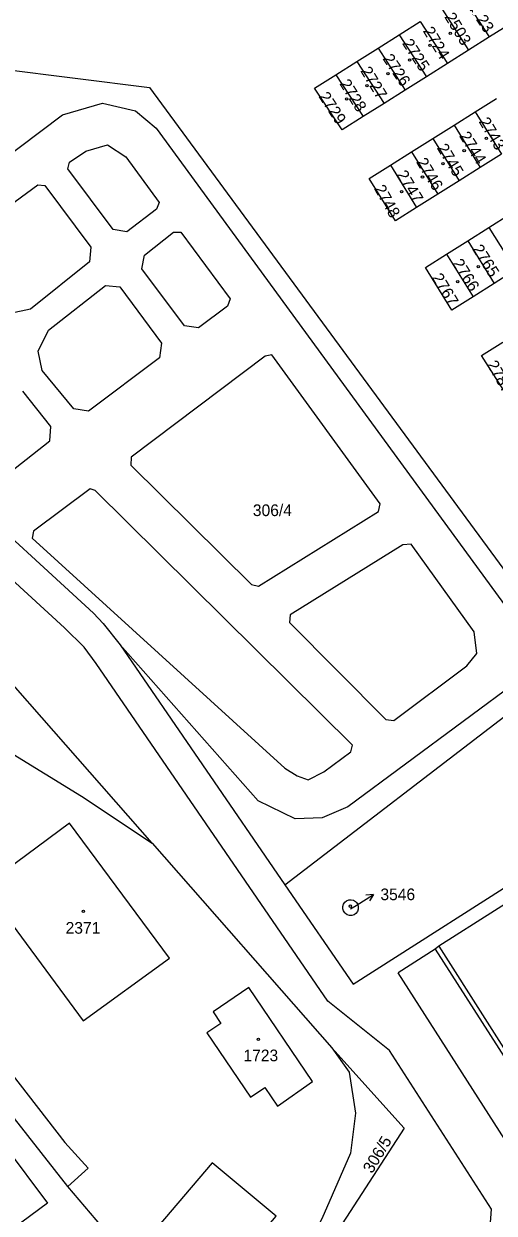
# Model space of a CAD drawing. Extents: x -679220 to -673243, y -1075091 to -1066557.
# Drawn here: x -676246.6 to -676178, y -1072555.7 to -1072382.5 of the extents above; entities that cross this region are included whole.
import ezdxf

# ---------------------------------------------------------------- set-up
doc = ezdxf.new("R2010")
doc.units = 0
for name, color, linetype in [('Hranice parcel', 7, 'Continuous'), ('Parcelní čísla', 7, 'Continuous'), ('Pop  PČ popisy', 7, 'Continuous'), ('Vnitřní kresba', 7, 'Continuous'), ('Značky budov', 7, 'Continuous')]:
    doc.layers.add(name, color=color, linetype=linetype)

msp = doc.modelspace()

# ---------------------------------------------------------------- linework, layer by layer
at = {"layer": 'Hranice parcel'}
for p, q in [((-676178.71, -1072384.44), (-676182.66, -1072378.34)), ((-676185.73, -1072380.27), (-676181.78, -1072386.37)), ((-676191.87, -1072384.13), (-676188.8, -1072382.2)), ((-676188.8, -1072382.2), (-676184.85, -1072388.31)), ((-676175.65, -1072382.51), (-676178.71, -1072384.44)), ((-676194.96, -1072386.07), (-676191.87, -1072384.13)), ((-676191.87, -1072384.13), (-676187.91, -1072390.24)), ((-676178.71, -1072384.44), (-676181.78, -1072386.37)), ((-676198.03, -1072388), (-676194.96, -1072386.07)), ((-676194.96, -1072386.07), (-676190.98, -1072392.18)), ((-676181.78, -1072386.37), (-676184.85, -1072388.31)), ((-676201.11, -1072389.94), (-676198.03, -1072388)), ((-676198.03, -1072388), (-676194.04, -1072394.11)), ((-676184.85, -1072388.31), (-676187.91, -1072390.24)), ((-676201.11, -1072389.94), (-676197.1, -1072396.04)), ((-676187.91, -1072390.24), (-676190.98, -1072392.18)), ((-676190.98, -1072392.18), (-676194.04, -1072394.11)), ((-676180.79, -1072395.35), (-676177.71, -1072393.41)), ((-676194.04, -1072394.11), (-676197.1, -1072396.04)), ((-676183.88, -1072397.29), (-676180.79, -1072395.35)), ((-676180.79, -1072395.35), (-676176.98, -1072401.52)), ((-676186.98, -1072399.23), (-676183.88, -1072397.29)), ((-676183.88, -1072397.29), (-676180.07, -1072403.46)), ((-676190.07, -1072401.17), (-676186.98, -1072399.23)), ((-676186.98, -1072399.23), (-676183.16, -1072405.41)), ((-676193.16, -1072403.11), (-676190.07, -1072401.17)), ((-676190.07, -1072401.17), (-676186.25, -1072407.35)), ((-676176.98, -1072401.52), (-676180.07, -1072403.46)), ((-676193.16, -1072403.11), (-676189.34, -1072409.29)), ((-676180.07, -1072403.46), (-676183.16, -1072405.41)), ((-676183.16, -1072405.41), (-676186.25, -1072407.35)), ((-676186.25, -1072407.35), (-676189.34, -1072409.29)), ((-676178.81, -1072412.19), (-676175.74, -1072410.25)), ((-676181.89, -1072414.14), (-676178.81, -1072412.19)), ((-676178.81, -1072412.19), (-676174.94, -1072418.38)), ((-676184.96, -1072416.09), (-676181.89, -1072414.14)), ((-676181.89, -1072414.14), (-676178.03, -1072420.33)), ((-676184.96, -1072416.09), (-676181.11, -1072422.28)), ((-676174.94, -1072418.38), (-676178.03, -1072420.33)), ((-676178.03, -1072420.33), (-676181.11, -1072422.28)), ((-676208.52, -1072507.9), (-676175.83, -1072482.87)), ((-676227.86, -1072501.86), (-676201.67, -1072531.67)), ((-676231.08, -1072562.45), (-676240.15, -1072551.88))]:
    msp.add_line(p, q, dxfattribs=at)
for points in [[(-676227.86, -1072501.86), (-676299.88, -1072419.89), (-676371.63, -1072338.06)], [(-676393.87, -1072354.27), (-676392.79, -1072356.37), (-676350.62, -1072411.11), (-676336.27, -1072423.2), (-676320.05, -1072433.48), (-676310.5, -1072438.74), (-676297.87, -1072456.58), (-676292.66, -1072479.44), (-676278.01, -1072497.19), (-676240.58, -1072545.43), (-676237.18, -1072549.2), (-676240.15, -1072551.88)], [(-676249.92, -1072389.1), (-676228.26, -1072391.78), (-676166.55, -1072475.76), (-676169.49, -1072478.01)], [(-676197.1, -1072396.04), (-676200.17, -1072397.98), (-676204.19, -1072391.88), (-676201.11, -1072389.94)], [(-676292.07, -1072402.99), (-676279.41, -1072419.22), (-676277.22, -1072423.73), (-676275.71, -1072427.4), (-676272.62, -1072432.59), (-676272.04, -1072433.35), (-676258.47, -1072448.08), (-676256.31, -1072450.13), (-676236.39, -1072468.37), (-676234.99, -1072469.86), (-676232.52, -1072472.99), (-676208.52, -1072507.9)], [(-676189.34, -1072409.29), (-676192.42, -1072411.23), (-676196.25, -1072405.05), (-676193.16, -1072403.11)], [(-676181.11, -1072422.28), (-676184.19, -1072424.23), (-676188.03, -1072418.03), (-676184.96, -1072416.09)], [(-676172.83, -1072435.02), (-676175.93, -1072436.98), (-676179.86, -1072430.85), (-676176.77, -1072428.9)], [(-676179.64, -1072571.39), (-676178.45, -1072555.16), (-676193.28, -1072532.03), (-676202.29, -1072524.88), (-676236.01, -1072475.68), (-676237.75, -1072473.29), (-676240.63, -1072470.5), (-676259.07, -1072453.6)], [(-676240.15, -1072551.88), (-676280.98, -1072499.86), (-676296, -1072482.45), (-676303.18, -1072461.34)], [(-676254.72, -1072484.88), (-676238.18, -1072494.99), (-676227.86, -1072501.86)], [(-676225.34, -1072518.59), (-676239.89, -1072498.95), (-676252.37, -1072508.19), (-676237.91, -1072527.72), (-676225.34, -1072518.59)], [(-676208.52, -1072507.9), (-676198.57, -1072522.38), (-676170.54, -1072504.52), (-676161.87, -1072507.92), (-676139.81, -1072542.54), (-676135.25, -1072539.65)], [(-676136.5, -1072570.82), (-676098.44, -1072546.68), (-676102.53, -1072540.16), (-676108.2, -1072531.13), (-676132.8, -1072546.95), (-676137.84, -1072550.19), (-676139.52, -1072551.27), (-676140.87, -1072552.14), (-676144.06, -1072547.18), (-676144.87, -1072545.92), (-676146.85, -1072542.85), (-676143.02, -1072540.41), (-676162.81, -1072509.22), (-676166.7, -1072511.75), (-676169.87, -1072506.55), (-676186.1, -1072516.87), (-676159.97, -1072557.94)], [(-676199.55, -1072510.23), (-676199.23, -1072510.12), (-676198.89, -1072510.1), (-676198.55, -1072510.18), (-676198.26, -1072510.36), (-676198.1, -1072510.52), (-676197.92, -1072510.81), (-676197.84, -1072511.14), (-676197.85, -1072511.48), (-676197.97, -1072511.81), (-676198.17, -1072512.08), (-676198.44, -1072512.29), (-676198.77, -1072512.39), (-676199.11, -1072512.39), (-676199.44, -1072512.29), (-676199.72, -1072512.1), (-676199.8, -1072512.02), (-676199.99, -1072511.73), (-676200.09, -1072511.41), (-676200.1, -1072511.06), (-676200, -1072510.74), (-676199.81, -1072510.45), (-676199.55, -1072510.23)], [(-676213.54, -1072538.86), (-676211.47, -1072537.46), (-676209.6, -1072540.16), (-676204.48, -1072536.57), (-676213.79, -1072522.87), (-676218.96, -1072526.44), (-676217.84, -1072528.1), (-676219.9, -1072529.5), (-676213.54, -1072538.86)], [(-676201.67, -1072531.67), (-676199.17, -1072535.19), (-676198.24, -1072541.19), (-676198.95, -1072546.98), (-676203.16, -1072556.56), (-676210.92, -1072570.88), (-676218.12, -1072581.78), (-676236.74, -1072601.09), (-676236.52, -1072604.92), (-676236.33, -1072610.64)], [(-676201.67, -1072531.67), (-676191.15, -1072543.36), (-676235.07, -1072611.09)], [(-676257.12, -1072538.94), (-676255.51, -1072537.76), (-676243.1, -1072554.3), (-676269.14, -1072573.49), (-676269.31, -1072573.26)], [(-676223.04, -1072571.81), (-676209.82, -1072556.18), (-676219.13, -1072548.39), (-676231.08, -1072562.45)]]:
    msp.add_lwpolyline(points, dxfattribs=at)
at = {"layer": 'Pop  PČ popisy'}
for p, q in [((-676198.15, -1072510.91), (-676195.6, -1072509.32)), ((-676195.6, -1072509.32), (-676196.72, -1072509.43)), ((-676195.6, -1072509.32), (-676196.19, -1072510.27)), ((-676198.97, -1072511.43), (-676198.15, -1072510.91))]:
    msp.add_line(p, q, dxfattribs=at)
at = {"layer": 'Vnitřní kresba'}
for p, q in [((-676240.9, -1072395.77), (-676235.08, -1072394.07)), ((-676235.08, -1072394.07), (-676230.3, -1072395.19)), ((-676230.3, -1072395.19), (-676227.26, -1072397.74)), ((-676273.2, -1072420.02), (-676240.9, -1072395.77)), ((-676227.26, -1072397.74), (-676170.61, -1072475.28)), ((-676237.51, -1072401.06), (-676234.36, -1072400.14)), ((-676234.36, -1072400.14), (-676231.72, -1072401.9)), ((-676239.89, -1072402.67), (-676237.51, -1072401.06)), ((-676231.72, -1072401.9), (-676226.82, -1072408.54)), ((-676240.13, -1072403.64), (-676239.89, -1072402.67)), ((-676233.52, -1072412.5), (-676240.13, -1072403.64)), ((-676256.76, -1072415.01), (-676244.53, -1072405.96)), ((-676244.53, -1072405.96), (-676243.52, -1072406.08)), ((-676243.52, -1072406.08), (-676236.78, -1072415.08)), ((-676226.82, -1072408.54), (-676227.23, -1072409.54)), ((-676227.23, -1072409.54), (-676231.53, -1072412.83)), ((-676231.53, -1072412.83), (-676233.52, -1072412.5)), ((-676228.99, -1072416.2), (-676224.76, -1072412.88)), ((-676224.76, -1072412.88), (-676223.7, -1072412.86)), ((-676223.7, -1072412.86), (-676216.52, -1072422.57)), ((-676236.78, -1072415.08), (-676237.01, -1072417.18)), ((-676237.01, -1072417.18), (-676245.59, -1072424.08)), ((-676229.36, -1072418.19), (-676228.99, -1072416.2)), ((-676223.15, -1072426.53), (-676229.36, -1072418.19)), ((-676242.94, -1072427.16), (-676234.66, -1072420.66)), ((-676234.66, -1072420.66), (-676232.59, -1072420.82)), ((-676232.59, -1072420.82), (-676226.5, -1072429.03)), ((-676216.52, -1072422.57), (-676216.87, -1072423.65)), ((-676245.59, -1072424.08), (-676248.55, -1072424.7)), ((-676216.87, -1072423.65), (-676221.12, -1072426.8)), ((-676244.49, -1072430.19), (-676242.94, -1072427.16)), ((-676221.12, -1072426.8), (-676223.15, -1072426.53)), ((-676226.5, -1072429.03), (-676226.78, -1072431.15)), ((-676243.9, -1072433.04), (-676244.49, -1072430.19)), ((-676226.78, -1072431.15), (-676237.16, -1072438.94)), ((-676211.41, -1072430.92), (-676230.9, -1072445.62)), ((-676210.43, -1072430.72), (-676211.41, -1072430.92)), ((-676194.63, -1072452.44), (-676210.43, -1072430.72)), ((-676239.28, -1072438.6), (-676243.9, -1072433.04)), ((-676242.61, -1072441.15), (-676246.69, -1072436.04)), ((-676237.16, -1072438.94), (-676239.28, -1072438.6)), ((-676242.78, -1072443.25), (-676242.61, -1072441.15)), ((-676251.91, -1072450.4), (-676242.78, -1072443.25)), ((-676230.9, -1072445.62), (-676230.96, -1072446.82)), ((-676230.96, -1072446.82), (-676213.41, -1072464.16)), ((-676236.89, -1072450.26), (-676245.15, -1072456.43)), ((-676236.15, -1072450.51), (-676236.89, -1072450.26)), ((-676198.67, -1072487.56), (-676236.15, -1072450.51)), ((-676212.36, -1072464.41), (-676194.88, -1072453.53)), ((-676194.88, -1072453.53), (-676194.63, -1072452.44)), ((-676245.15, -1072456.43), (-676245.32, -1072457.43)), ((-676245.32, -1072457.43), (-676208.52, -1072490.94)), ((-676191.32, -1072458.41), (-676207.78, -1072468.59)), ((-676190.12, -1072458.33), (-676191.32, -1072458.41)), ((-676180.96, -1072471.08), (-676190.12, -1072458.33)), ((-676213.41, -1072464.16), (-676212.36, -1072464.41)), ((-676207.78, -1072468.59), (-676207.86, -1072469.73)), ((-676207.86, -1072469.73), (-676193.83, -1072483.83)), ((-676180.58, -1072474.23), (-676180.96, -1072471.08)), ((-676212.42, -1072495.67), (-676232.52, -1072472.99)), ((-676182, -1072476.02), (-676180.58, -1072474.23)), ((-676170.61, -1072475.28), (-676199.37, -1072496.57)), ((-676192.64, -1072483.99), (-676182, -1072476.02)), ((-676193.83, -1072483.83), (-676192.64, -1072483.99)), ((-676202.85, -1072491.46), (-676198.9, -1072488.54)), ((-676198.9, -1072488.54), (-676198.67, -1072487.56)), ((-676208.52, -1072490.94), (-676206.74, -1072492.04)), ((-676206.74, -1072492.04), (-676205.15, -1072492.65)), ((-676205.15, -1072492.65), (-676202.85, -1072491.46)), ((-676207.03, -1072498.3), (-676212.42, -1072495.67)), ((-676199.37, -1072496.57), (-676203.11, -1072498.19)), ((-676203.11, -1072498.19), (-676207.03, -1072498.3)), ((-676186.62, -1072517.27), (-676192.01, -1072520.73)), ((-676186.1, -1072516.87), (-676186.62, -1072517.27)), ((-676186.62, -1072517.27), (-676160.43, -1072558.32)), ((-676166.87, -1072560.09), (-676192.01, -1072520.73))]:
    msp.add_line(p, q, dxfattribs=at)
at = {"layer": 'Značky budov'}
for centre in [(-676184.43, -1072383.9), (-676187.37, -1072385.65), (-676190.35, -1072387.81), (-676193.51, -1072389.78), (-676196.57, -1072391.53), (-676199.54, -1072393.47), (-676179.17, -1072399.19), (-676182.41, -1072401.01), (-676185.5, -1072402.91), (-676188.48, -1072404.85), (-676191.53, -1072406.97), (-676180.36, -1072417.91), (-676183.34, -1072420.07), (-676198.99, -1072511.03), (-676237.88, -1072511.78), (-676212.38, -1072530.41)]:
    msp.add_circle(centre, 0.175, dxfattribs=at)

# ---------------------------------------------------------------- texts
at = {"layer": 'Parcelní čísla'}
for s, rotation, p in [('2723', 303, (-676182.12, -1072379.75)), ('2503', 301, (-676185.34, -1072381.51)), ('2724', 301, (-676188.47, -1072383.56)), ('2725', 303, (-676191.5, -1072385.37)), ('2726', 304, (-676194.35, -1072387.61)), ('2727', 301, (-676197.58, -1072389.37)), ('2728', 302, (-676200.63, -1072391.24)), ('2729', 303, (-676203.67, -1072393.11)), ('2743', 301, (-676180.34, -1072396.76)), ('2744', 302, (-676183.19, -1072398.86)), ('2745', 301, (-676186.44, -1072400.6)), ('2746', 301, (-676189.45, -1072402.65)), ('2747', 301, (-676192.32, -1072404.48)), ('2748', 299, (-676195.57, -1072406.53)), ('2765', 302, (-676181.3, -1072415.31)), ('2766', 302, (-676184.2, -1072417.39)), ('2767', 301, (-676187.19, -1072419.47)), ('2787', 300, (-676179.17, -1072432.14)), ('306/5', 59, (-676195.82, -1072550.07))]:
    msp.add_text(s, height=1.7, rotation=rotation, dxfattribs=at).set_placement(p)
for s, p in [('306/4', (-676213.19, -1072454.22)), ('3546', (-676194.61, -1072510.16)), ('2371', (-676240.47, -1072515.04)), ('1723', (-676214.56, -1072533.62))]:
    msp.add_text(s, height=1.7, dxfattribs=at).set_placement(p)

doc.saveas('drawing.dxf')
